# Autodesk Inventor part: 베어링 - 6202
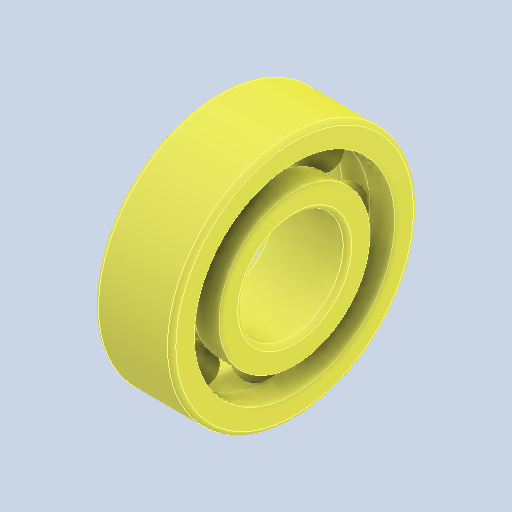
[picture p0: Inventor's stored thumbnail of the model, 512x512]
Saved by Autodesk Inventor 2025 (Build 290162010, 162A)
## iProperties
Created: 2024-07
Part Number: 베어링 - 6202
Material: 강, 연강
Description: 깊은 그루브 볼 베어링
Document SubType Name: Modeling
Designer: 학생
Density: 7.86 g/cm^3
Appearance: 기본값
Author: jhkim
Sending System: Autodesk Inventor 2025
Preprocessor: ST-DEVELOPER v20
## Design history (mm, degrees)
feature "Solid1"
feature "Solid1:1"
feature "Solid1:2"
feature "Solid1:3"
feature "Solid1:4"
feature "Solid1:5"
feature "Solid1:6"
feature "Solid1:7"
feature "Solid1:8"
feature "Solid1:9"
node "솔리드1"
node "솔리드2"
node "솔리드3"
node "솔리드4"
node "솔리드5"
node "솔리드6"
node "솔리드7"
node "솔리드8"
node "솔리드9"
node "솔리드10"
